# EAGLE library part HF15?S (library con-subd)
SUB-D
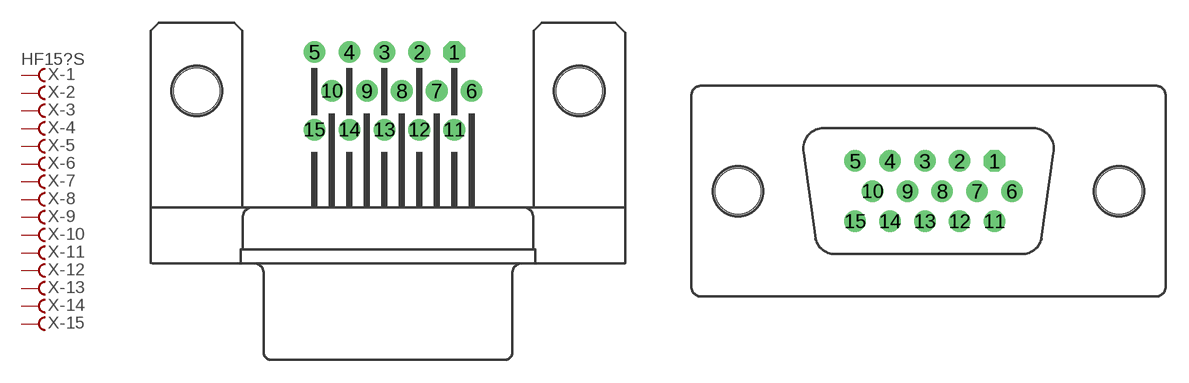
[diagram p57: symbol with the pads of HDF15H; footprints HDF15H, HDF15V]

Designator prefix X; gates -1=FV -2=F -3=F -4=F -5=F -6=F -7=F -8=F -9=F -10=F -11=F -12=F -13=F -14=F -15=F

## HF15HS (OC_FARNELL: unknown; OC_NEWARK: unknown)  [HDF15H]
1  -1:F  pas
2  -2:F  pas
3  -3:F  pas
4  -4:F  pas
5  -5:F  pas
6  -6:F  pas
7  -7:F  pas
8  -8:F  pas
9  -9:F  pas
10  -10:F  pas
11  -11:F  pas
12  -12:F  pas
13  -13:F  pas
14  -14:F  pas
15  -15:F  pas

## HF15VS (OC_FARNELL: unknown; OC_NEWARK: unknown)  [HDF15V]
Pads as for HDF15H

## Footprint HDF15H (pad centres in mm)
SUB-D
drill 0.9 octagon: 1 4.329,2.54
drill 0.9 round: 2 2.043,2.54; 3 -0.243,2.54; 4 -2.529,2.54; 5 -4.815,2.54; 6 5.472,0; 7 3.186,0; 8 0.9,0; 9 -1.386,0; 10 -3.672,0; 11 4.329,-2.54; 12 2.043,-2.54; 13 -0.243,-2.54; 14 -2.529,-2.54; 15 -4.815,-2.54
hole 3 at -12.5,0
hole 3 at 12.5,0

## Footprint HDF15V (pad centres in mm)
SUB-D
drill 0.9 octagon: 1 4.329,1.98
drill 0.9 round: 2 2.043,1.98; 3 -0.243,1.98; 4 -2.529,1.98; 5 -4.815,1.98; 6 5.472,0; 7 3.186,0; 8 0.9,0; 9 -1.386,0; 10 -3.672,0; 11 4.329,-1.98; 12 2.043,-1.98; 13 -0.243,-1.98; 14 -2.529,-1.98; 15 -4.815,-1.98
hole 3 at -12.5,0
hole 3 at 12.5,0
